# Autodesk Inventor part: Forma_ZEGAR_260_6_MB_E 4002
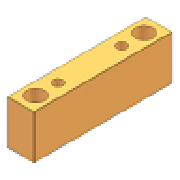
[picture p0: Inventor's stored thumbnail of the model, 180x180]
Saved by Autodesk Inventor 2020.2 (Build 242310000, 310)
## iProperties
Manager: www.cadconsulting.pl
Company: Fabian Stasiak CAD Consulting
Created: 2014-02
Part Number: Forma_ZEGAR_260_6_MB_E 4002
Material: S 55 C
Description: Spacer Block
Document SubType Name: Modeling
Designer: F.Stasiak
Standard Revision: 1
Manufacturer: DME
Language: pl-PL
Size Designation: 496x346x76
Categories: <MemberInstance><Categories><Category DisplayName="Forma wtryskowa" InternalName="349578f2-f4d4-4954-8c09-8e99297a61c0" Mnemonic="MOLD"><Category DisplayName="P
Density: 7.85 g/cm^3
Appearance: Orange (Pale)
Catalog Web Link: www.expertbooks.pl
IsCustomPart: 1
Author: F.Stasiak
Subject: Zbiór ćwiczeń. Autodesk Inventor 2020. Kurs Professional
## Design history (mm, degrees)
sketch "Sketch1"
  geometry: L1 (-111, 248)-(-173, 248); L2 (-173, 248)-(-173, -248); L3 (-173, -248)-(-111, -248); L4 (-111, -248)-(-111, 248); L5 (173, 248)-(173, -248); L6 (111, -248)-(111, 248); L7 (111, 248)-(173, 248); L8 (111, -248)-(173, -248); 7 further points
  constraints: 16 end point, 3 parallel, 2 horizontal alignment, 2 midpoint, 2 perpendicular, 1 horizontal, 1 vertical
  dimensions: "d85" = 496 distance between parallel lines of L3 L1 (= L); "d86" = 62 distance between parallel lines of L4 L2 (= W_); "d88" = 62 distance between parallel lines of L5 L6 (= W_); "d89" = 173 distance from line of point (0, 0) L2 (= 0.5 x M_W); "d93" = 496 distance between parallel lines of L8 L7 (= L); "d94" = 173 distance from line of point (0, 0) L5 (= 0.5 x M_W); "d98" = 165 vertical distance of point (-137, 165) point (0, 0) (= 0.5 x S1_L); "d100" = 137 horizontal distance of point (-137, 165) point (0, 0) (= 0.5 x S1_W); "d101" = 137 horizontal distance of point (137, 165) point (0, 0) (= 0.5 x S1_W); "d102" = 165 vertical distance of point (0, 0) point (137, 165) (= 0.5 x S1_L); "d103" = 137 horizontal distance of point (-137, 208) point (0, 0) (= 0.5 x LS_W); "d105" = 208 vertical distance of point (-137, 208) point (0, 0) (= 0.5 x LS_L); "d106" = 137 horizontal distance of point (0, 0) point (137, 208) (= 0.5 x LS_W); "d107" = 208 vertical distance of point (137, 208) point (0, 0) (= 0.5 x LS_L)
extrude "Extrusion1" new body sketch "Sketch1" distance "d20" = 76 (= H_); taper "d30" = 0 deg
extrude "Extrusion2" join sketch "Sketch1" distance "d95" = 76 (= H_); taper "d96" = 0 deg
hole "Hole1" sketch "Sketch1" diameter "d129" = 18 (= S1_d1); stored, may be unused: countersink angle "d133" = 90 deg, drill point angle "d135" = 0 deg; dims "d130" = 6, "d131" = 4, "d132" = 2, "d134" = 76 (= H_)
pattern_linear "Rectangular Pattern1" dims "d156" = 330 (computed from S1_L, Ns)
hole "Hole2" sketch "Sketch1" diameter "d108" = 42 (= LS_d); stored, may be unused: countersink angle "d112" = 90 deg, drill point angle "d114" = 0 deg; dims "d109" = 6, "d110" = 4, "d111" = 2, "d113" = 76 (= H_)
pattern_linear "Rectangular Pattern2" dims "d138" = 416 (computed from LS_L, Nl)
hole "Hole3" sketch "Sketch1" diameter "d122" = 18 (= S1_d1); stored, may be unused: countersink angle "d126" = 90 deg, drill point angle "d128" = 0 deg; dims "d123" = 6, "d124" = 4, "d125" = 2, "d127" = 76 (= H_)
pattern_linear "Rectangular Pattern3" dims "d153" = 330 (computed from S1_L, Ns)
hole "Hole4" sketch "Sketch1" diameter "d115" = 42 (= LS_d); stored, may be unused: countersink angle "d119" = 90 deg, drill point angle "d121" = 0 deg; dims "d116" = 6, "d117" = 4, "d118" = 2, "d120" = 76 (= H_)
pattern_linear "Rectangular Pattern4" dims "d150" = 416 (computed from LS_L, Nl)
workplane "Work Plane1"
workplane "Work Plane2"
chamfer "Chamfer1" distance "d82" = 0.5; stored, may be unused: second distance "d83" = 2, angle "d84" = 45 deg
chamfer "Chamfer2" distance "d157" = 0.5; stored, may be unused: second distance "d158" = 2, angle "d159" = 45 deg
body "Solid1"
other parameters: "L" = 496 [user parameter; used in 2 equation terms], "W_" = 62 [user parameter; used in 2 equation terms], "H_" = 76 [user parameter; used in 7 equation terms], "M_W" = 346 [user parameter; used in 2 equation terms], "S1_W" = 274 [user parameter; used in 2 equation terms], "S1_d1" = 18 [user parameter; used in 2 equation terms], "LS_L" = 416 [user parameter; used in 4 equation terms], "LS_W" = 274 [user parameter; used in 2 equation terms], "LS_d" = 42 [user parameter; used in 2 equation terms], "d160" = 0, "d161" = 76 (= H_)
